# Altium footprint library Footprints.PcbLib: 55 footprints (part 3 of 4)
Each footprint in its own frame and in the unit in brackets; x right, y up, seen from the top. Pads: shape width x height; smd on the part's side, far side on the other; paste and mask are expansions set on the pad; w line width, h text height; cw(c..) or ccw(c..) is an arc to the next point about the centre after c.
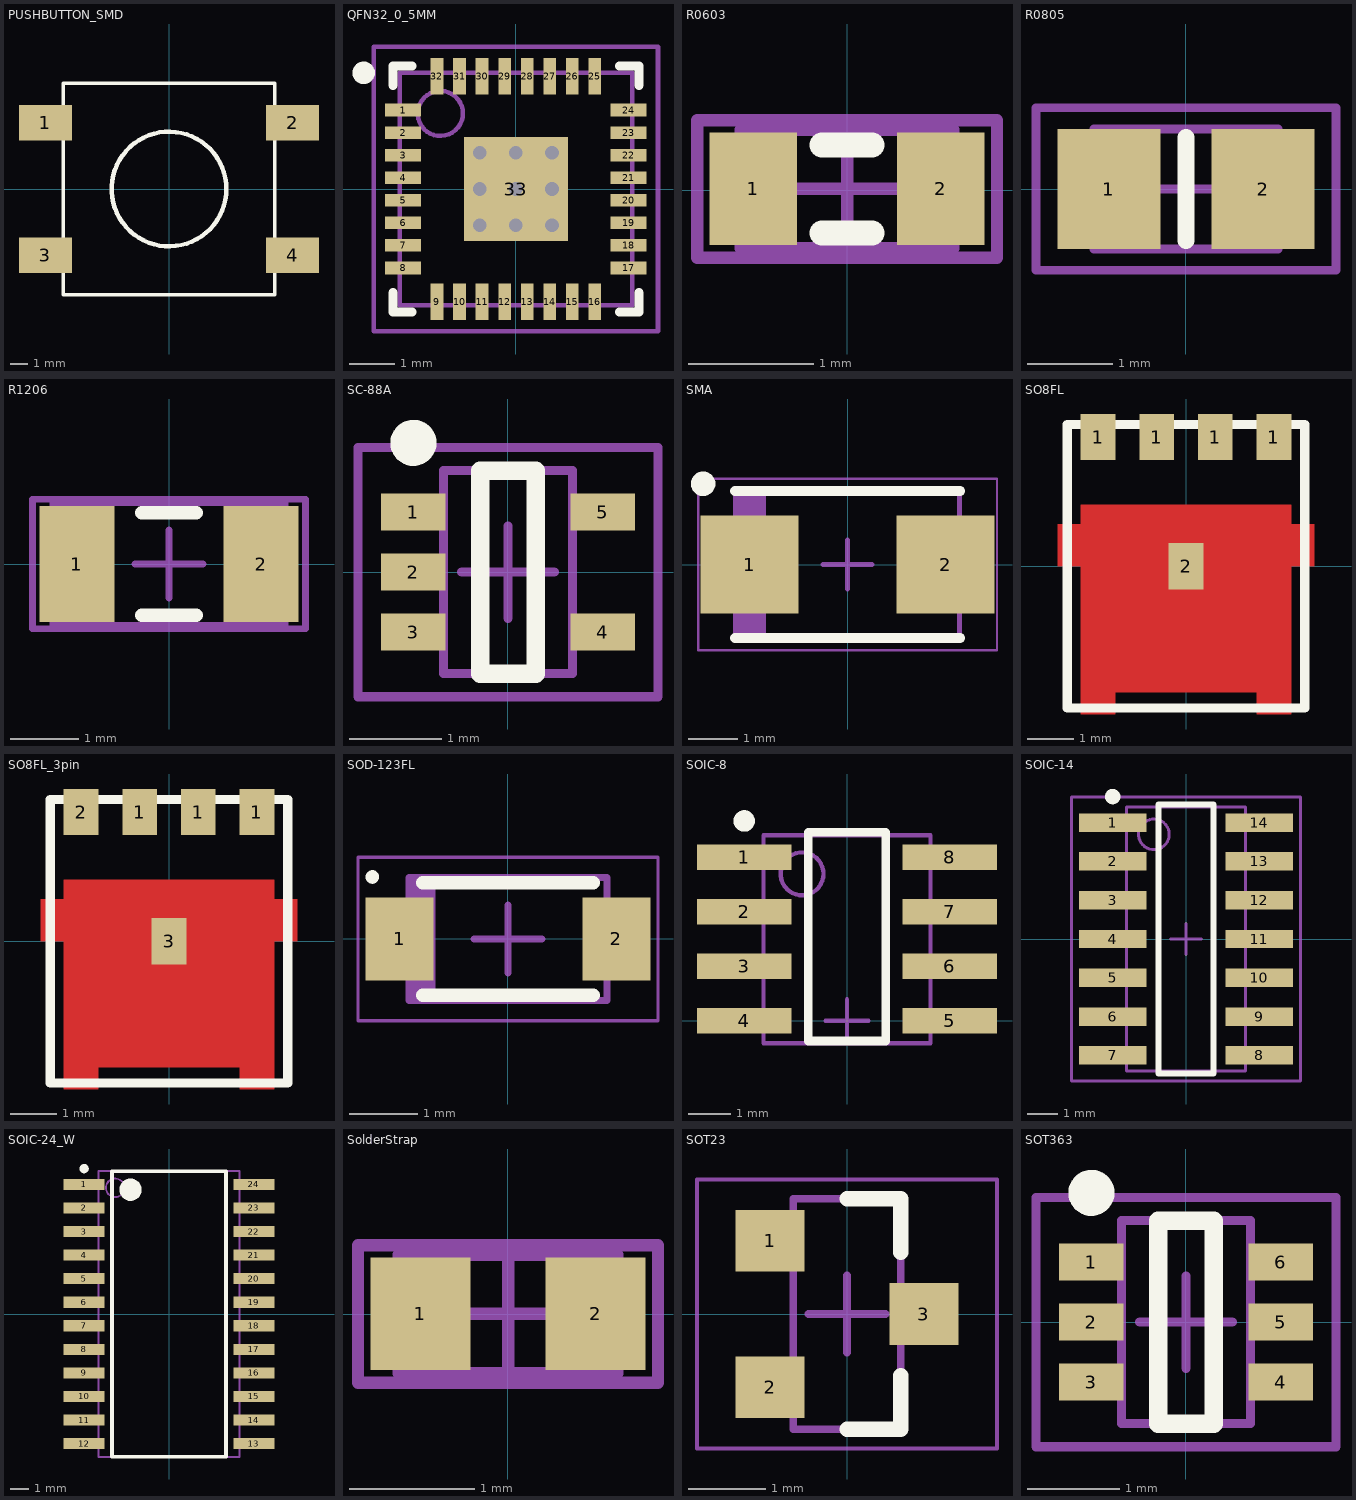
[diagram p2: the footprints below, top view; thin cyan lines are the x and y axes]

## PUSHBUTTON_SMD [mm]
height 5
pads (4):
  rect 3x2 smd: 1(-7,3.75) 2(7,3.75) 3(-7,-3.75) 4(7,-3.75)
Top Overlay:
  circle w0.254: c0,0 r3.25
  lines w0.2: -6,-6 -6,6 6,6 6,-6 -6,-6
3D body: height 4.7, standoff -0.15, extent -8,-5.575 7.9,5.825

## QFN32_0_5MM [mm] "QFN, 32-Leads, Body 5x5mm, Pitch 0.5mm, IPC Medium Density"
height 1
pads (33):
  rect 0.8x0.28 smd: 1(-2.5,1.75) 2(-2.5,1.25) 3(-2.5,0.75) 4(-2.5,0.25) 5(-2.5,-0.25) 6(-2.5,-0.75) 7(-2.5,-1.25) 8(-2.5,-1.75) 17(2.5,-1.75) 18(2.5,-1.25) 19(2.5,-0.75) 20(2.5,-0.25) 21(2.5,0.25) 22(2.5,0.75) 23(2.5,1.25) 24(2.5,1.75)
  rect 0.28x0.8 smd: 9(-1.75,-2.5) 10(-1.25,-2.5) 11(-0.75,-2.5) 12(-0.25,-2.5) 13(0.25,-2.5) 14(0.75,-2.5) 15(1.25,-2.5) 16(1.75,-2.5) 25(1.75,2.5) 26(1.25,2.5) 27(0.75,2.5) 28(0.25,2.5) 29(-0.25,2.5) 30(-0.75,2.5) 31(-1.25,2.5) 32(-1.75,2.5)
  rect 2.3x2.3 smd: 33(0,0)
via 0,0 diameter 0.7 hole 0.3
via 0,-0.8 diameter 0.7 hole 0.3
via 0,0.8 diameter 0.7 hole 0.3
via 0.8,0.8 diameter 0.7 hole 0.3
via -0.8,0.8 diameter 0.7 hole 0.3
via -0.8,0 diameter 0.7 hole 0.3
via -0.8,-0.8 diameter 0.7 hole 0.3
via 0.8,-0.8 diameter 0.7 hole 0.3
via 0.8,0 diameter 0.7 hole 0.3
Top Overlay:
  circle w0.25: c-3.375,2.575 r0.125
  lines w0.2: -2.725,-2.3 -2.725,-2.725 -2.3,-2.725 ; -2.725,2.3 -2.725,2.725 -2.3,2.725 ; 2.3,-2.725 2.725,-2.725 2.725,-2.3 ; 2.3,2.725 2.725,2.725 2.725,2.3
Mechanical 13:
  circle w0.1: c-1.675,1.675 r0.5
  lines w0.1: -2.575,-2.575 2.575,-2.575 2.575,2.575 -2.575,2.575 -2.575,-2.575
Mechanical 15:
  lines w0.1: -0.5,0 0.5,0 ; 0,-0.5 0,0.5 ; -3.15,-3.15 3.15,-3.15 3.15,3.15 -3.15,3.15 -3.15,-3.15
3D body: height 0.8, standoff -0.05, extent -2.5,-2.5 2.5,2.5

## R0603 [mm]
height 0.9
pads (2):
  rect 0.7x0.9 smd: 1(-0.751,0.008) 2(0.749,0.008)
Top Overlay:
  lines w0.2: -0.201,-0.342 0.199,-0.342 ; -0.201,0.358 0.199,0.358
Mechanical 13:
  lines w0.1: -0.851,-0.467 -0.851,0.483 0.849,0.483 0.849,-0.467 -0.851,-0.467
Mechanical 15:
  lines w0.1: -0.476,0.008 0.474,0.008 ; -0.001,-0.467 -0.001,0.483 ; -1.201,-0.542 -1.201,0.558 1.199,0.558 1.199,-0.542 -1.201,-0.542
3D body: height 0.5, standoff 0, extent -0.801,-0.392 0.799,0.408

## R0805 [mm] "Chip Resistor, Body 2.0x1.2mm, IPC Medium Density"
height 0.7
pads (2):
  rect 1.2x1.4 smd: 1(-0.9,0) 2(0.9,0)
Top Overlay:
  lines w0.2: 0,-0.6 0,0.6
Mechanical 13:
  lines w0.1: -1.075,-0.7 1.075,-0.7 1.075,0.7 -1.075,0.7 -1.075,-0.7
Mechanical 15:
  lines w0.1: -0.5,0 0.5,0 ; 0,-0.5 0,0.5 ; -1.75,-0.95 1.75,-0.95 1.75,0.95 -1.75,0.95 -1.75,-0.95
3D body: height 0.5, standoff 0, extent -1,-0.6 1,0.6

## R1206 [mm] "Chip Resistor, Body 3.2x1.6mm, IPC High Density"
height 1.3
pads (2):
  rect 1.1x1.7 smd: 1(-1.35,0) 2(1.35,0)
Top Overlay:
  lines w0.2: -0.4,-0.75 0.4,-0.75 ; -0.4,0.75 0.4,0.75
Mechanical 13:
  lines w0.1: -1.7,-0.9 1.7,-0.9 1.7,0.9 -1.7,0.9 -1.7,-0.9
Mechanical 15:
  lines w0.1: -0.5,0 0.5,0 ; 0,-0.5 0,0.5 ; -2,-0.95 2,-0.95 2,0.95 -2,0.95 -2,-0.95
3D body: height 0.6, standoff 0, extent -1.6,-0.8 1.6,0.8

## SC-88A [mm] "SOT353, 5-Leads, Body 2x1.3mm, Pitch 0.65mm, Lead Span 2.1mm, IPC Medium Density"
height 1.1
pads (5):
  rect 0.7x0.4 smd mask+0: 1(-1.025,0.65) 2(-1.025,0) 3(-1.025,-0.65)
  rect 0.7x0.4 smd: 4(1.025,-0.65) 5(1.025,0.65)
Top Overlay:
  circle w0.25: c-1.025,1.4 r0.125
  lines w0.2: -0.3,-1.1 -0.3,1.1 0.3,1.1 0.3,-1.1 -0.3,-1.1
Top Solder:
  rectangle: -1.475,-0.95 -0.575,0.95
Mechanical 13:
  lines w0.1: -0.7,-1.1 0.7,-1.1 0.7,1.1 -0.7,1.1 -0.7,-1.1
Mechanical 15:
  lines w0.1: -0.5,0 0.5,0 ; 0,-0.5 0,0.5 ; -1.625,-1.35 1.625,-1.35 1.625,1.35 -1.625,1.35 -1.625,-1.35
3D body: height 1, standoff 0, extent -1.15,-1.05 1.15,1.05

## SMA [mm] "Molded Diode, 2-Leads, Body 4.31x2.60mm, IPC Medium Density"
height 2.2
pads (2):
  rect 2x2 smd: 1(-2,0) 2(2,0)
Top Overlay:
  circle w0.25: c-2.95,1.65 r0.125
  lines w0.2: -2.3,-1.5 2.3,-1.5 ; -2.3,1.5 2.3,1.5
Mechanical 13:
  rectangle: -2.285,-1.46 -1.67,1.46
  lines w0.1: -2.285,-1.46 -2.285,1.46 2.285,1.46 2.285,-1.46 -2.285,-1.46
Mechanical 15:
  lines w0.05: -3.05,-1.75 -3.05,1.75 3.05,1.75 3.05,-1.75 -3.05,-1.75
  lines w0.1: -0.5,0 0.5,0 ; 0,-0.5 0,0.5
3D body: height 2.6, standoff 0.03, extent -2.75,-1.4 2.75,1.4

## SO8FL [mm]
height 1
pads (5):
  rect 0.75x1 smd: 1(-1.905,2.795) 1(-0.635,2.795) 1(0.635,2.795) 1(1.905,2.795) 2(0,0)
Top Layer:
  region: -2.28,1.33 -2.28,0.905 -2.775,0.905 -2.775,0 -2.28,0 -2.28,-3.2 -1.53,-3.2 -1.53,-2.725 1.53,-2.725 1.53,-3.2 2.28,-3.2 2.28,0 2.775,0 2.775,0.905 2.28,0.905 2.28,1.33
Top Overlay:
  lines w0.2: -2.57,-3.07 2.57,-3.07 2.57,3.07 -2.57,3.07 -2.57,-3.07
3D body: height 1.13, standoff 0, extent -2.575,-3.05 2.575,3.1

## SO8FL_3pin [mm]
height 1
pads (5):
  rect 0.75x1 smd: 1(-0.635,2.795) 1(0.635,2.795) 1(1.905,2.795) 2(-1.905,2.795) 3(0,0)
Top Layer:
  region: -2.28,1.33 -2.28,0.905 -2.775,0.905 -2.775,0 -2.28,0 -2.28,-3.2 -1.53,-3.2 -1.53,-2.725 1.53,-2.725 1.53,-3.2 2.28,-3.2 2.28,0 2.775,0 2.775,0.905 2.28,0.905 2.28,1.33
Top Overlay:
  lines w0.2: -2.57,-3.07 -2.57,3.07 2.57,3.07 2.57,-3.07 -2.57,-3.07
3D body: height 1, standoff 0, extent -2.57,-3.07 2.57,3.07

## SOD-123FL [mm] "Molded Diode, 2-Leads, Body 2.70x1.65mm, IPC Medium Density"
height 1
pads (2):
  rect 1x1.22 smd: 1(-1.59,0) 2(1.59,0)
Top Overlay:
  circle w0.1: c-1.99,0.91 r0.05
  lines w0.2: -1.25,-0.825 1.25,-0.825 ; -1.25,0.825 1.25,0.825
Mechanical 13:
  rectangle: -1.45,-0.9 -1.06,0.9
  lines w0.1: -1.45,-0.9 -1.45,0.9 1.45,0.9 1.45,-0.9 -1.45,-0.9
Mechanical 15:
  lines w0.05: -2.2,-1.2 -2.2,1.2 2.2,1.2 2.2,-1.2 -2.2,-1.2
  lines w0.1: -0.5,0 0.5,0 ; 0,-0.5 0,0.5
3D body: height 1, standoff 0, extent -1.45,-0.9 1.45,0.9

## SOIC-8 [mm] "8-Pin Small Outline Integrated Circuit 1.27 mm Pitch, IPC Medium Density"
height 1.75
pads (8):
  rect 2.2x0.6 smd: 1(-2.4,3.81) 2(-2.4,2.54) 3(-2.4,1.27) 4(-2.4,0) 5(2.4,0) 6(2.4,1.27) 7(2.4,2.54) 8(2.4,3.81)
Top Overlay:
  circle w0.25: c-2.4,4.66 r0.125
  lines w0.2: -0.9,-0.475 0.9,-0.475 0.9,4.4 -0.9,4.4 -0.9,-0.475
Mechanical 13:
  circle w0.1: c-1.05,3.425 r0.5
  lines w0.1: -1.95,-0.525 1.95,-0.525 1.95,4.325 -1.95,4.325 -1.95,-0.525
Mechanical 15:
  lines w0.1: -0.5,0 0.5,0 ; 0,-0.5 0,0.5
3D body: height 1.63, standoff 0, extent -3,-0.525 3,4.375

## SOIC-14 [mm] "14-Pin Small Outline Integrated Circuit 1.27 mm Pitch, IPC Medium Density"
height 1.75
pads (14):
  rect 2.2x0.6 smd: 1(-2.4,3.81) 2(-2.4,2.54) 3(-2.4,1.27) 4(-2.4,0) 5(-2.4,-1.27) 6(-2.4,-2.54) 7(-2.4,-3.81) 8(2.4,-3.81) 9(2.4,-2.54) 10(2.4,-1.27) 11(2.4,0) 12(2.4,1.27) 13(2.4,2.54) 14(2.4,3.81)
Top Overlay:
  circle w0.25: c-2.4,4.66 r0.125
  lines w0.2: -0.9,-4.4 -0.9,4.4 0.9,4.4 0.9,-4.4 -0.9,-4.4
Mechanical 13:
  circle w0.1: c-1.05,3.425 r0.5
  lines w0.1: -1.95,-4.325 -1.95,4.325 1.95,4.325 1.95,-4.325 -1.95,-4.325
Mechanical 15:
  lines w0.1: -0.5,0 0.5,0 ; 0,-0.5 0,0.5 ; -3.75,-4.65 -3.75,4.65 3.75,4.65 3.75,-4.65 -3.75,-4.65
3D body: height 1.75, standoff 0, extent -1.95,-4.325 1.95,4.325

## SOIC-24_W [mm] "SOIC, 24-Leads, Body 15,30x7,47mm, Pitch 1,27mm, IPC Medium Density"
height 2.65
pads (24):
  rect 2.2x0.6 smd: 1(-4.575,6.985) 2(-4.575,5.715) 3(-4.575,4.445) 4(-4.575,3.175) 5(-4.575,1.905) 6(-4.575,0.635) 7(-4.575,-0.635) 8(-4.575,-1.905) 9(-4.575,-3.175) 10(-4.575,-4.445) 11(-4.575,-5.715) 12(-4.575,-6.985) 13(4.575,-6.985) 14(4.575,-5.715) 15(4.575,-4.445) 16(4.575,-3.175) 17(4.575,-1.905) 18(4.575,-0.635) 19(4.575,0.635) 20(4.575,1.905) 21(4.575,3.175) 22(4.575,4.445) 23(4.575,5.715) 24(4.575,6.985)
Top Overlay:
  circle w0.25: c-4.575,7.835 r0.125
  circle w0.6: c-2.075,6.7 r0.3
  lines w0.2: -3.075,-7.7 -3.075,7.7 3.075,7.7 3.075,-7.7 -3.075,-7.7
Mechanical 13:
  circle w0.1: c-2.9,6.8 r0.5
  lines w0.1: -3.8,-7.7 -3.8,7.7 3.8,7.7 3.8,-7.7 -3.8,-7.7
3D body: height 2.65, standoff 0, extent -5.15,-7.75 5.15,7.75

## SolderStrap [mm] "Solder Strap"
height 1.3
pads (2):
  rect 0.8x0.9 smd: 1(-0.7,0) 2(0.7,0)
Top Solder:
  rectangle: -0.325,-0.55 0.475,0.55
Mechanical 13:
  lines w0.1: -0.875,-0.475 -0.875,0.475 0.875,0.475 0.875,-0.475 -0.875,-0.475
Mechanical 15:
  lines w0.1: -0.475,0 0.475,0 ; 0,-0.475 0,0.475 ; -1.2,-0.55 -1.2,0.55 1.2,0.55 1.2,-0.55 -1.2,-0.55
3D body: height 0.5, standoff 0, extent -0.875,-0.475 0.875,0.475

## SOT23 [mm] "SOT23, 3-Leads, Body 2.90x2.37mm, Pitch 0.95mm, IPC Medium Density"
height 1.1
pads (3):
  rect 0.9x0.8 smd: 1(-1,0.95) 2(-1,-0.95) 3(1,0)
Top Overlay:
  lines w0.2: 0,-1.5 0.7,-1.5 0.7,-0.8 ; 0,1.5 0.7,1.5 0.7,0.8
Mechanical 13:
  lines w0.1: -0.7,-1.5 -0.7,1.5 0.7,1.5 0.7,-1.5 -0.7,-1.5
Mechanical 15:
  lines w0.05: -1.95,-1.75 -1.95,1.75 1.95,1.75 1.95,-1.75 -1.95,-1.75
  lines w0.1: -0.5,0 0.5,0 ; 0,-0.5 0,0.5
3D body: height 0.94, standoff -0.04, extent -1.299,-1.45 1.249,1.47

## SOT363 [mm] "SOT363, 6-Leads, Body 2x1.3mm, Pitch 0.65mm, Lead Span 2.1mm, IPC Medium Density"
height 1.1
pads (6):
  rect 0.7x0.4 smd mask+0: 1(-1.025,0.65) 2(-1.025,0) 3(-1.025,-0.65) 4(1.025,-0.65) 5(1.025,0) 6(1.025,0.65)
Top Overlay:
  circle w0.25: c-1.025,1.4 r0.125
  lines w0.2: -0.3,-1.1 0.3,-1.1 0.3,1.1 -0.3,1.1 -0.3,-1.1
Top Solder:
  rectangle: -1.475,-0.95 -0.575,0.95
  rectangle: 0.575,-0.95 1.475,0.95
Mechanical 13:
  lines w0.1: -0.7,-1.1 -0.7,1.1 0.7,1.1 0.7,-1.1 -0.7,-1.1
Mechanical 15:
  lines w0.1: -0.5,0 0.5,0 ; 0,-0.5 0,0.5 ; -1.625,-1.35 -1.625,1.35 1.625,1.35 1.625,-1.35 -1.625,-1.35
3D body: height 1, standoff 0, extent -1.15,-1.05 1.15,1.05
